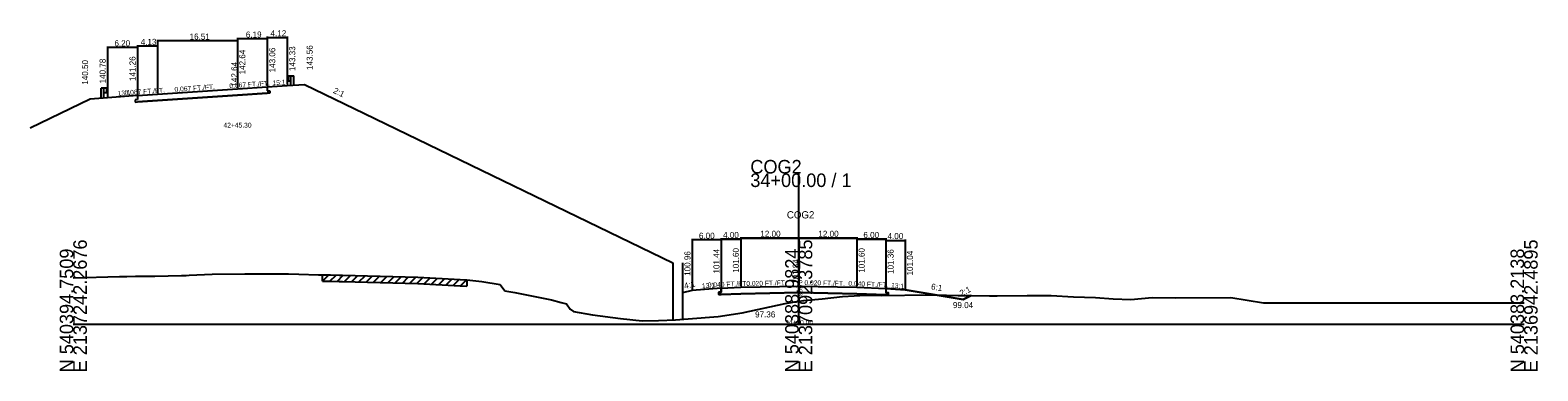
# Model space of a CAD drawing. Extents: x -13397 to 2303, y -10 to 39059.
# Drawn here: x 991.1 to 1302.8, y 7990.3 to 8060.8 of the extents above; entities that cross this region are included whole.
import ezdxf

# ---------------------------------------------------------------- set-up
doc = ezdxf.new("R2010")
doc.units = 0
for name, color, linetype in [('Level 20', 7, 'Continuous'), ('Level 5', 7, 'Continuous'), ('Level 53', 7, 'Continuous'), ('Level 54', 7, 'Continuous'), ('Level 55', 7, 'Continuous'), ('Level 7', 7, 'Continuous'), ('RD_GPK_XS_Cell', 7, 'Continuous'), ('RD_XS_EwShp', 7, 'Continuous'), ('RD_XS_ExGround', 7, 'Continuous'), ('RD_XS_ExPaveRet', 7, 'Continuous'), ('RD_XS_MedBWall', 7, 'Continuous'), ('RD_XS_Pave', 7, 'Continuous'), ('RD_XS_TX_Baseline', 7, 'Continuous'), ('RD_XS_TX_Elev_EX', 7, 'Continuous'), ('RD_XS_TX_Elev_PR', 7, 'Continuous'), ('RD_XS_TX_Station', 7, 'Continuous')]:
    doc.layers.add(name, color=color, linetype=linetype)

msp = doc.modelspace()

# ---------------------------------------------------------------- linework, layer by layer
at = {"layer": 'Level 20'}
for p, q in [((1033.92, 8059.21), (1033.92, 8048.84)), ((1033.92, 8059.21), (1033.92, 8048.84)), ((1040.11, 8059.48), (1040.11, 8049.26)), ((1040.11, 8059.28), (1044.23, 8059.28)), ((1040.11, 8059.21), (1040.11, 8049.26)), ((1040.11, 8059.21), (1040.11, 8049.26)), ((1044.23, 8059.48), (1044.23, 8049.53)), ((1007.08, 8057.41), (1007.08, 8046.98)), ((1013.28, 8057.21), (1007.08, 8057.21)), ((1013.28, 8057.69), (1013.28, 8047.46)), ((1017.41, 8057.49), (1013.28, 8057.49)), ((1013.28, 8057.41), (1013.28, 8047.46)), ((1017.41, 8058.79), (1017.41, 8047.74)), ((1017.41, 8058.79), (1017.41, 8047.74)), ((1033.92, 8058.59), (1017.41, 8058.59)), ((1033.92, 8058.59), (1017.41, 8058.59)), ((1017.41, 8057.69), (1017.41, 8047.74)), ((1040.11, 8059.01), (1033.92, 8059.01)), ((1040.11, 8059.01), (1033.92, 8059.01)), ((1033.92, 8058.79), (1033.92, 8048.84)), ((1033.92, 8058.79), (1033.92, 8048.84)), ((1044.26, 8051.14), (1044.37, 8051.24)), ((1044.26, 8051.04), (1044.37, 8050.95)), ((1044.26, 8050.61), (1044.37, 8050.71)), ((1044.26, 8050.51), (1044.37, 8050.42)), ((1044.38, 8051.24), (1044.46, 8051.25)), ((1044.38, 8050.42), (1044.46, 8050.4)), ((1044.39, 8050.91), (1044.39, 8050.75)), ((1044.46, 8051.32), (1044.46, 8050.34)), ((1044.46, 8051.32), (1045.01, 8051.32)), ((1044.46, 8050.34), (1045.01, 8050.34)), ((1045.01, 8049.33), (1045.01, 8051.32)), ((1045.01, 8051.32), (1045.57, 8051.32)), ((1045.57, 8049.33), (1045.57, 8051.32)), ((1007.08, 8046.78), (1003.47, 8046.5)), ((1005.75, 8046.78), (1005.75, 8048.77)), ((1006.3, 8048.77), (1005.75, 8048.77)), ((1006.3, 8046.78), (1006.3, 8048.77)), ((1006.86, 8048.77), (1006.3, 8048.77)), ((1006.86, 8047.8), (1006.3, 8047.8)), ((1006.86, 8048.77), (1006.86, 8047.8)), ((1006.93, 8048.7), (1006.86, 8048.71)), ((1006.93, 8047.87), (1006.86, 8047.86)), ((1006.93, 8048.36), (1006.93, 8048.21)), ((1007.06, 8048.6), (1006.95, 8048.69)), ((1007.06, 8048.5), (1006.95, 8048.41)), ((1007.06, 8048.07), (1006.95, 8048.16)), ((1007.06, 8047.97), (1006.95, 8047.88)), ((1013.28, 8047.26), (1007.08, 8046.78)), ((1013.28, 8047.26), (1017.41, 8047.54)), ((1013.28, 8047.26), (1013.28, 8046.43)), ((1017.41, 8047.54), (1033.92, 8048.64)), ((1033.92, 8047.31), (1017.41, 8046.21)), ((1033.92, 8047.31), (1017.41, 8046.21)), ((1017.41, 8046.21), (1033.92, 8047.31)), ((1017.41, 8046.21), (1033.92, 8047.31)), ((1033.92, 8048.64), (1040.11, 8049.06)), ((1040.11, 8047.73), (1033.92, 8047.31)), ((1033.92, 8047.31), (1040.11, 8047.73)), ((1033.92, 8047.31), (1040.11, 8047.73)), ((1040.11, 8049.06), (1044.23, 8049.33)), ((1040.11, 8049.06), (1040.11, 8048.23)), ((1040.11, 8048.23), (1040.62, 8048.26)), ((1040.62, 8047.76), (1040.11, 8047.73)), ((1040.62, 8048.26), (1040.62, 8047.76)), ((1044.23, 8049.33), (1047.84, 8049.56)), ((1047.84, 8049.56), (1060.21, 8043.56)), ((1003.47, 8046.5), (991.08, 8040.5)), ((1013.28, 8046.43), (1012.76, 8046.4)), ((1012.76, 8046.4), (1012.76, 8045.9)), ((1012.76, 8045.9), (1013.28, 8045.93)), ((1017.41, 8046.21), (1013.28, 8045.93)), ((1017.41, 8046.21), (1013.28, 8045.93)), ((1013.28, 8045.93), (1017.41, 8046.21)), ((1060.21, 8043.56), (1124, 8012.63))]:
    msp.add_line(p, q, dxfattribs=at)
for centre, radius, start, end in [((1044.3, 8051.09), 0.0651, 129.0336, 230.9663), ((1044.3, 8050.56), 0.0651, 129.0336, 230.9663), ((1044.32, 8050.75), 0.0651, 302.9895, 0), ((1044.38, 8051.22), 0.026, 90, 129.0505), ((1044.32, 8050.91), 0.0651, 0, 45), ((1044.38, 8050.44), 0.026, 230.9496, 270), ((1006.93, 8048.67), 0.026, 50.9495, 90), ((1006.99, 8048.36), 0.0651, 135, 180), ((1006.99, 8048.21), 0.0651, 180, 237.0105), ((1006.93, 8047.9), 0.026, 270, 309.0504), ((1007.02, 8048.55), 0.0651, 309.0337, 50.9664), ((1007.02, 8048.02), 0.0651, 309.0337, 50.9664)]:
    msp.add_arc(centre, radius, start, end, dxfattribs=at)
at = {"layer": 'Level 5'}
for p, q in [((1134, 8006.61), (1133.5, 8006.59)), ((1133.5, 8006.59), (1133.5, 8006.09)), ((1133.5, 8006.09), (1134, 8006.11)), ((1134, 8007.44), (1134, 8006.61)), ((1138, 8006.27), (1134, 8006.11)), ((1138, 8006.27), (1134, 8006.11)), ((1138, 8006.27), (1134, 8006.11)), ((1134, 8006.11), (1138, 8006.27)), ((1150, 8006.51), (1138, 8006.27)), ((1150, 8006.51), (1138, 8006.27)), ((1150, 8006.51), (1138, 8006.27)), ((1138, 8006.27), (1150, 8006.51)), ((1138, 8006.27), (1150, 8006.51)), ((1162, 8006.27), (1150, 8006.51)), ((1162, 8006.27), (1150, 8006.51)), ((1150, 8006.51), (1162, 8006.27)), ((1150, 8006.51), (1162, 8006.27)), ((1150, 8006.51), (1162, 8006.27)), ((1168, 8006.03), (1162, 8006.27)), ((1162, 8006.27), (1168, 8006.03)), ((1162, 8006.27), (1168, 8006.03)), ((1162, 8006.27), (1168, 8006.03)), ((1168, 8007.36), (1168, 8006.53)), ((1168, 8006.53), (1168.5, 8006.51)), ((1168.5, 8006.01), (1168, 8006.03)), ((1168.5, 8006.51), (1168.5, 8006.01))]:
    msp.add_line(p, q, dxfattribs=at)
at = {"layer": 'Level 54'}
for p, q in [((1128, 8017.59), (1128, 8007.16)), ((1134, 8017.39), (1128, 8017.39)), ((1134, 8017.75), (1134, 8007.64)), ((1134, 8017.75), (1134, 8007.64)), ((1134, 8017.75), (1134, 8007.64)), ((1134, 8017.75), (1134, 8007.64)), ((1134, 8017.59), (1134, 8007.64)), ((1134, 8017.55), (1138, 8017.55)), ((1134, 8017.55), (1138, 8017.55)), ((1134, 8017.55), (1138, 8017.55)), ((1138, 8017.55), (1134, 8017.55)), ((1138, 8017.99), (1138, 8007.8)), ((1138, 8017.99), (1138, 8007.8)), ((1138, 8017.99), (1138, 8007.8)), ((1138, 8017.99), (1138, 8007.8)), ((1138, 8017.99), (1138, 8007.8)), ((1138, 8017.79), (1150, 8017.79)), ((1138, 8017.79), (1150, 8017.79)), ((1138, 8017.79), (1150, 8017.79)), ((1150, 8017.79), (1138, 8017.79)), ((1150, 8017.79), (1138, 8017.79)), ((1138, 8017.75), (1138, 8007.8)), ((1138, 8017.75), (1138, 8007.8)), ((1138, 8017.75), (1138, 8007.8)), ((1138, 8017.75), (1138, 8007.8)), ((1150, 8017.99), (1150, 8008.04)), ((1150, 8017.99), (1150, 8008.04)), ((1150, 8017.99), (1150, 8008.04)), ((1150, 8017.99), (1150, 8008.04)), ((1150, 8017.99), (1150, 8008.04)), ((1150, 8017.99), (1150, 8008.04)), ((1150, 8017.99), (1150, 8008.04)), ((1150, 8017.99), (1150, 8008.04)), ((1150, 8017.99), (1150, 8008.04)), ((1150, 8017.99), (1150, 8008.04)), ((1150, 8017.79), (1162, 8017.79)), ((1150, 8017.79), (1162, 8017.79)), ((1162, 8017.79), (1150, 8017.79)), ((1162, 8017.79), (1150, 8017.79)), ((1162, 8017.79), (1150, 8017.79)), ((1162, 8017.99), (1162, 8007.8)), ((1162, 8017.99), (1162, 8007.8)), ((1162, 8017.99), (1162, 8007.8)), ((1162, 8017.99), (1162, 8007.8)), ((1162, 8017.99), (1162, 8007.8)), ((1162, 8017.75), (1162, 8007.8)), ((1162, 8017.75), (1162, 8007.8)), ((1162, 8017.75), (1162, 8007.8)), ((1162, 8017.75), (1162, 8007.8)), ((1162, 8017.55), (1168, 8017.55)), ((1168, 8017.55), (1162, 8017.55)), ((1168, 8017.55), (1162, 8017.55)), ((1168, 8017.55), (1162, 8017.55)), ((1168, 8017.75), (1168, 8007.56)), ((1168, 8017.75), (1168, 8007.56)), ((1168, 8017.75), (1168, 8007.56)), ((1168, 8017.75), (1168, 8007.56)), ((1168, 8017.51), (1168, 8007.56)), ((1168, 8017.31), (1172, 8017.31)), ((1172, 8017.51), (1172, 8007.24))]:
    msp.add_line(p, q, dxfattribs=at)
at = {"layer": 'Level 7'}
for p, q in [((1128, 8006.96), (1126, 8006.46)), ((1126, 8006.46), (1126, 8000.98)), ((1134, 8007.44), (1128, 8006.96)), ((1168, 8007.36), (1172, 8007.04)), ((1172, 8007.04), (1184, 8005.04)), ((1184, 8005.04), (1185.68, 8005.88))]:
    msp.add_line(p, q, dxfattribs=at)
at = {"layer": 'RD_GPK_XS_Cell'}
for p, q in [((1150, 8000), (1150, 8031.14)), ((1000, 8000), (1150, 8000)), ((1150, 8000), (1300, 8000))]:
    msp.add_line(p, q, dxfattribs=at)
at = {"layer": 'RD_XS_EwShp'}
for points in [[(1126, 8006.46), (1126, 8000.98), (1127.14, 8001.04), (1133.38, 8001.53), (1138.3, 8002.31), (1147.23, 8004.26), (1150, 8004.7), (1151.08, 8004.87), (1154.83, 8005.22), (1159.05, 8005.66), (1163.86, 8005.96), (1167.22, 8005.9), (1176.65, 8006.03), (1178.21, 8006.01), (1172, 8007.04), (1168, 8007.36), (1168, 8006.53), (1168.5, 8006.51), (1168.5, 8006.01), (1168, 8006.03), (1162, 8006.27), (1150, 8006.51), (1138, 8006.27), (1134, 8006.11), (1133.5, 8006.09), (1133.5, 8006.59), (1134, 8006.61), (1134, 8007.44), (1128, 8006.96)], [(1182.97, 8005.92), (1185.68, 8005.88), (1184, 8005.04), (1178.21, 8006.01)]]:
    msp.add_lwpolyline(points, close=True, dxfattribs=at)
at = {"layer": 'RD_XS_ExGround'}
for p, q in [((1000, 8009.53), (1009.57, 8009.8)), ((1009.57, 8009.8), (1011.08, 8009.84)), ((1011.08, 8009.84), (1012.88, 8009.88)), ((1012.88, 8009.88), (1016.86, 8009.91)), ((1016.86, 8009.91), (1022.4, 8010.02)), ((1022.4, 8010.02), (1023.35, 8010.01)), ((1023.35, 8010.01), (1023.98, 8010.1)), ((1023.98, 8010.1), (1028.75, 8010.3)), ((1028.75, 8010.3), (1035.46, 8010.38)), ((1035.46, 8010.38), (1044.52, 8010.35)), ((1044.52, 8010.35), (1046.64, 8010.32)), ((1046.64, 8010.32), (1050.71, 8010.2)), ((1050.71, 8010.2), (1051.56, 8010.17)), ((1051.56, 8010.17), (1053.18, 8010.14)), ((1053.18, 8010.14), (1054.95, 8010.11)), ((1054.95, 8010.11), (1055.65, 8010.09)), ((1055.65, 8010.09), (1071.23, 8009.7)), ((1071.23, 8009.7), (1079.98, 8009.2)), ((1079.98, 8009.2), (1081.37, 8009.14)), ((1081.37, 8009.14), (1084.46, 8008.77)), ((1084.46, 8008.77), (1088.27, 8008.2)), ((1088.27, 8008.2), (1089.22, 8006.88)), ((1089.22, 8006.88), (1091.31, 8006.53)), ((1091.31, 8006.53), (1098.91, 8005)), ((1167.22, 8005.9), (1176.65, 8006.03)), ((1176.65, 8006.03), (1182.97, 8005.92)), ((1098.91, 8005), (1100.88, 8004.47)), ((1100.88, 8004.47), (1101.97, 8004.2)), ((1101.97, 8004.2), (1102.71, 8003.04)), ((1102.71, 8003.04), (1103.44, 8002.56)), ((1138.3, 8002.31), (1147.23, 8004.26)), ((1147.23, 8004.26), (1150, 8004.7)), ((1150, 8004.7), (1151.08, 8004.87)), ((1151.08, 8004.87), (1154.83, 8005.22)), ((1154.83, 8005.22), (1159.05, 8005.66)), ((1159.05, 8005.66), (1163.86, 8005.96)), ((1163.86, 8005.96), (1167.22, 8005.9)), ((1182.97, 8005.92), (1189.43, 8005.82)), ((1189.43, 8005.82), (1190.13, 8005.81)), ((1190.13, 8005.81), (1191.02, 8005.81)), ((1191.02, 8005.81), (1197.24, 8005.91)), ((1197.24, 8005.91), (1202.21, 8005.9)), ((1202.21, 8005.9), (1206.83, 8005.64)), ((1206.83, 8005.64), (1211.37, 8005.45)), ((1211.37, 8005.45), (1215, 8005.18)), ((1215, 8005.18), (1218.66, 8005.1)), ((1218.66, 8005.1), (1223.09, 8005.49)), ((1223.09, 8005.49), (1228.01, 8005.4)), ((1228.01, 8005.4), (1239.35, 8005.45)), ((1239.35, 8005.45), (1246.12, 8004.39)), ((1246.12, 8004.39), (1247.84, 8004.39)), ((1247.84, 8004.39), (1262.32, 8004.39)), ((1262.32, 8004.39), (1268.58, 8004.39)), ((1268.58, 8004.39), (1272.43, 8004.39)), ((1272.43, 8004.39), (1282.69, 8004.39)), ((1282.69, 8004.39), (1289.04, 8004.39)), ((1289.04, 8004.39), (1295.69, 8004.39)), ((1295.69, 8004.39), (1300, 8004.39)), ((1103.44, 8002.56), (1107.35, 8001.93)), ((1107.35, 8001.93), (1113.12, 8001.12)), ((1113.12, 8001.12), (1117.63, 8000.65)), ((1117.63, 8000.65), (1121.01, 8000.76)), ((1121.01, 8000.76), (1124.5, 8000.89)), ((1124.5, 8000.89), (1127.14, 8001.04)), ((1127.14, 8001.04), (1133.38, 8001.53)), ((1133.38, 8001.53), (1138.3, 8002.31))]:
    msp.add_line(p, q, dxfattribs=at)
at = {"layer": 'RD_XS_ExPaveRet'}
for p, q in [((1051.56, 8008.87), (1051.56, 8010.17)), ((1051.56, 8008.87), (1052.83, 8010.15)), ((1053.06, 8008.84), (1054.33, 8010.12)), ((1054.56, 8008.81), (1055.83, 8010.08)), ((1056.06, 8008.78), (1057.33, 8010.05)), ((1057.56, 8008.74), (1058.83, 8010.01)), ((1059.06, 8008.7), (1060.33, 8009.97)), ((1060.56, 8008.67), (1061.83, 8009.93)), ((1062.06, 8008.63), (1063.33, 8009.9)), ((1063.56, 8008.59), (1064.83, 8009.86)), ((1065.06, 8008.55), (1066.33, 8009.82)), ((1066.56, 8008.52), (1067.83, 8009.78)), ((1068.06, 8008.48), (1069.33, 8009.75)), ((1069.56, 8008.44), (1070.83, 8009.71)), ((1071.06, 8008.4), (1072.29, 8009.64)), ((1072.56, 8008.32), (1073.79, 8009.55)), ((1074.06, 8008.24), (1075.29, 8009.47)), ((1075.56, 8008.15), (1076.79, 8009.38)), ((1077.06, 8008.07), (1078.29, 8009.3)), ((1078.56, 8007.98), (1079.79, 8009.21)), ((1080.06, 8007.9), (1081.3, 8009.14)), ((1081.37, 8009.14), (1081.37, 8007.84)), ((1051.56, 8008.87), (1053.18, 8008.84)), ((1053.18, 8008.84), (1054.95, 8008.81)), ((1054.95, 8008.81), (1055.65, 8008.79)), ((1055.65, 8008.79), (1071.23, 8008.4)), ((1071.23, 8008.4), (1079.98, 8007.9)), ((1079.98, 8007.9), (1081.37, 8007.84))]:
    msp.add_line(p, q, dxfattribs=at)
at = {"layer": 'RD_XS_MedBWall'}
for p, q in [((1124, 8012.63), (1124, 8000.87)), ((1126, 8012.63), (1126, 8006.46))]:
    msp.add_line(p, q, dxfattribs=at)
at = {"layer": 'RD_XS_Pave'}
for p, q in [((1134, 8007.44), (1138, 8007.6)), ((1138, 8007.6), (1150, 8007.84)), ((1150, 8007.84), (1162, 8007.6)), ((1162, 8007.6), (1168, 8007.36))]:
    msp.add_line(p, q, dxfattribs=at)

# ---------------------------------------------------------------- texts
at = {"layer": 'Level 20'}
for s, height, p in [('16.51', 1.25, (1024.05, 8058.84)), ('16.51', 1.25, (1024.05, 8058.84)), ('6.19', 1.25, (1035.68, 8059.26)), ('6.19', 1.25, (1035.68, 8059.26)), ('4.12', 1.25, (1040.78, 8059.53)), ('6.20', 1.25, (1008.51, 8057.46)), ('4.13', 1.25, (1013.94, 8057.74)), ('42+45.30', 1, (1031.06, 8040.64))]:
    msp.add_text(s, height=height, dxfattribs=at).set_placement(p)
for s, height, rotation, p in [('142.64', 1.25, 90, (1035.58, 8051.64)), ('142.64', 1.25, 90, (1035.58, 8051.64)), ('143.06', 1.25, 90, (1041.76, 8052.06)), ('143.33', 1.25, 90, (1045.89, 8052.33)), ('143.56', 1.25, 90, (1049.5, 8052.56)), ('140.50', 1.25, 90, (1003.06, 8049.5)), ('140.78', 1.25, 90, (1006.68, 8049.78)), ('141.26', 1.25, 90, (1012.87, 8050.26)), (' 142.64', 1.25, 90, (1033.92, 8048.64)), ('0.067 FT./FT.', 1, 3.8341, (1032.31, 8048.79)), ('0.067 FT./FT.', 1, 3.8341, (1032.31, 8048.79)), ('15:1', 1, 3.7189, (1041.22, 8049.38)), ('13:1', 1, 4.4301, (1009.21, 8047.2)), ('0.067 FT./FT.', 1, 3.8234, (1010.64, 8047.34)), ('0.067 FT./FT.', 1, 3.8286, (1020.96, 8048.03)), ('0.067 FT./FT.', 1, 3.8286, (1020.96, 8048.03)), ('2:1', 1.25, 334.1298, (1053.62, 8047.87))]:
    msp.add_text(s, height=height, rotation=rotation, dxfattribs=at).set_placement(p)
at = {"layer": 'Level 53'}
for s, rotation, p in [('101.44', 90, (1133.62, 8010.44)), ('101.60', 90, (1137.63, 8010.6)), ('101.60', 90, (1137.63, 8010.6)), ('101.60', 90, (1137.63, 8010.6)), ('101.60', 90, (1163.63, 8010.6)), ('101.60', 90, (1163.63, 8010.6)), ('101.60', 90, (1163.63, 8010.6)), ('101.36', 90, (1169.62, 8010.36)), ('100.96', 90, (1127.62, 8009.96)), ('101.04', 90, (1173.62, 8010.04)), ('4:1', 14.0362, (1126.46, 8007.23)), ('6:1', 350.5377, (1177.3, 8007.17))]:
    msp.add_text(s, height=1.25, rotation=rotation, dxfattribs=at).set_placement(p)
for s, p in [('99.04', (1181.89, 8003.29)), ('97.36', (1140.98, 8001.36))]:
    msp.add_text(s, height=1.25, dxfattribs=at).set_placement(p)
at = {"layer": 'Level 54'}
for s, p in [('6.00', (1129.37, 8017.64)), ('4.00', (1134.37, 8017.8)), ('4.00', (1134.37, 8017.8)), ('4.00', (1134.37, 8017.8)), ('4.00', (1134.37, 8017.8)), ('12.00', (1142.07, 8018.04)), ('12.00', (1142.07, 8018.04)), ('12.00', (1142.07, 8018.04)), ('12.00', (1142.07, 8018.04)), ('12.00', (1142.07, 8018.04)), ('12.00', (1154.07, 8018.04)), ('12.00', (1154.07, 8018.04)), ('12.00', (1154.07, 8018.04)), ('12.00', (1154.07, 8018.04)), ('12.00', (1154.07, 8018.04)), ('6.00', (1163.37, 8017.8)), ('6.00', (1163.37, 8017.8)), ('6.00', (1163.37, 8017.8)), ('6.00', (1163.37, 8017.8)), ('4.00', (1168.37, 8017.56))]:
    msp.add_text(s, height=1.25, dxfattribs=at).set_placement(p)
at = {"layer": 'Level 55'}
for s, height, rotation, p in [('13:1', 1, 4.5739, (1130.03, 8007.37)), ('0.040 FT./FT.', 1, 2.2906, (1131.22, 8007.58)), ('0.040 FT./FT.', 1, 2.2906, (1131.22, 8007.58)), ('0.040 FT./FT.', 1, 2.2906, (1131.22, 8007.58)), ('0.040 FT./FT.', 1, 2.2906, (1131.22, 8007.58)), ('0.020 FT./FT.', 1, 1.1458, (1139.17, 8007.87)), ('0.020 FT./FT.', 1, 1.1458, (1139.17, 8007.87)), ('0.020 FT./FT.', 1, 1.1458, (1139.17, 8007.87)), ('0.020 FT./FT.', 1, 1.1458, (1139.17, 8007.87)), ('0.020 FT./FT.', 1, 1.1458, (1139.17, 8007.87)), ('0.020 FT./FT.', 1, 358.8542, (1151.18, 8008.07)), ('0.020 FT./FT.', 1, 358.8542, (1151.18, 8008.07)), ('0.020 FT./FT.', 1, 358.8542, (1151.18, 8008.07)), ('0.020 FT./FT.', 1, 358.8542, (1151.18, 8008.07)), ('0.020 FT./FT.', 1, 358.8542, (1151.18, 8008.07)), ('0.040 FT./FT.', 1, 357.7094, (1160.24, 8007.92)), ('0.040 FT./FT.', 1, 357.7094, (1160.24, 8007.92)), ('0.040 FT./FT.', 1, 357.7094, (1160.24, 8007.92)), ('0.040 FT./FT.', 1, 357.7094, (1160.24, 8007.92)), ('13:1', 1, 355.4261, (1169.07, 8007.53)), ('2:1', 1.25, 26.5651, (1183.66, 8005.71))]:
    msp.add_text(s, height=height, rotation=rotation, dxfattribs=at).set_placement(p)
at = {"layer": 'RD_GPK_XS_Cell'}
for s, p in [('34+00.00 / 1', (1140, 8028.34)), ('COG2', (1140, 8031.14))]:
    msp.add_text(s, height=2.8, dxfattribs=at).set_placement(p)
for s, p in [('N 540394.7509', (1000, 7990)), ('E 2137242.2676', (1002.8, 7990)), ('N 540388.9824', (1150, 7990)), ('E 2137092.3785', (1152.8, 7990)), ('N 540383.2138', (1300, 7990)), ('E 2136942.4895', (1302.8, 7990))]:
    msp.add_text(s, height=2.8, rotation=90, dxfattribs=at).set_placement(p)
at = {"layer": 'RD_XS_TX_Baseline'}
msp.add_text('COG2', height=1.5, dxfattribs=at).set_placement((1147.55, 8021.84))
at = {"layer": 'RD_XS_TX_Elev_EX'}
msp.add_text('98.70', height=1, rotation=90, dxfattribs=at).set_placement((1150.75, 8005.7))
at = {"layer": 'RD_XS_TX_Elev_PR'}
msp.add_text(' 101.84', height=1.25, rotation=90, dxfattribs=at).set_placement((1150, 8007.84))
at = {"layer": 'RD_XS_TX_Station'}
msp.add_text('34+00.00', height=1, dxfattribs=at).set_placement((1147.17, 7999.84))

doc.saveas('drawing.dxf')
